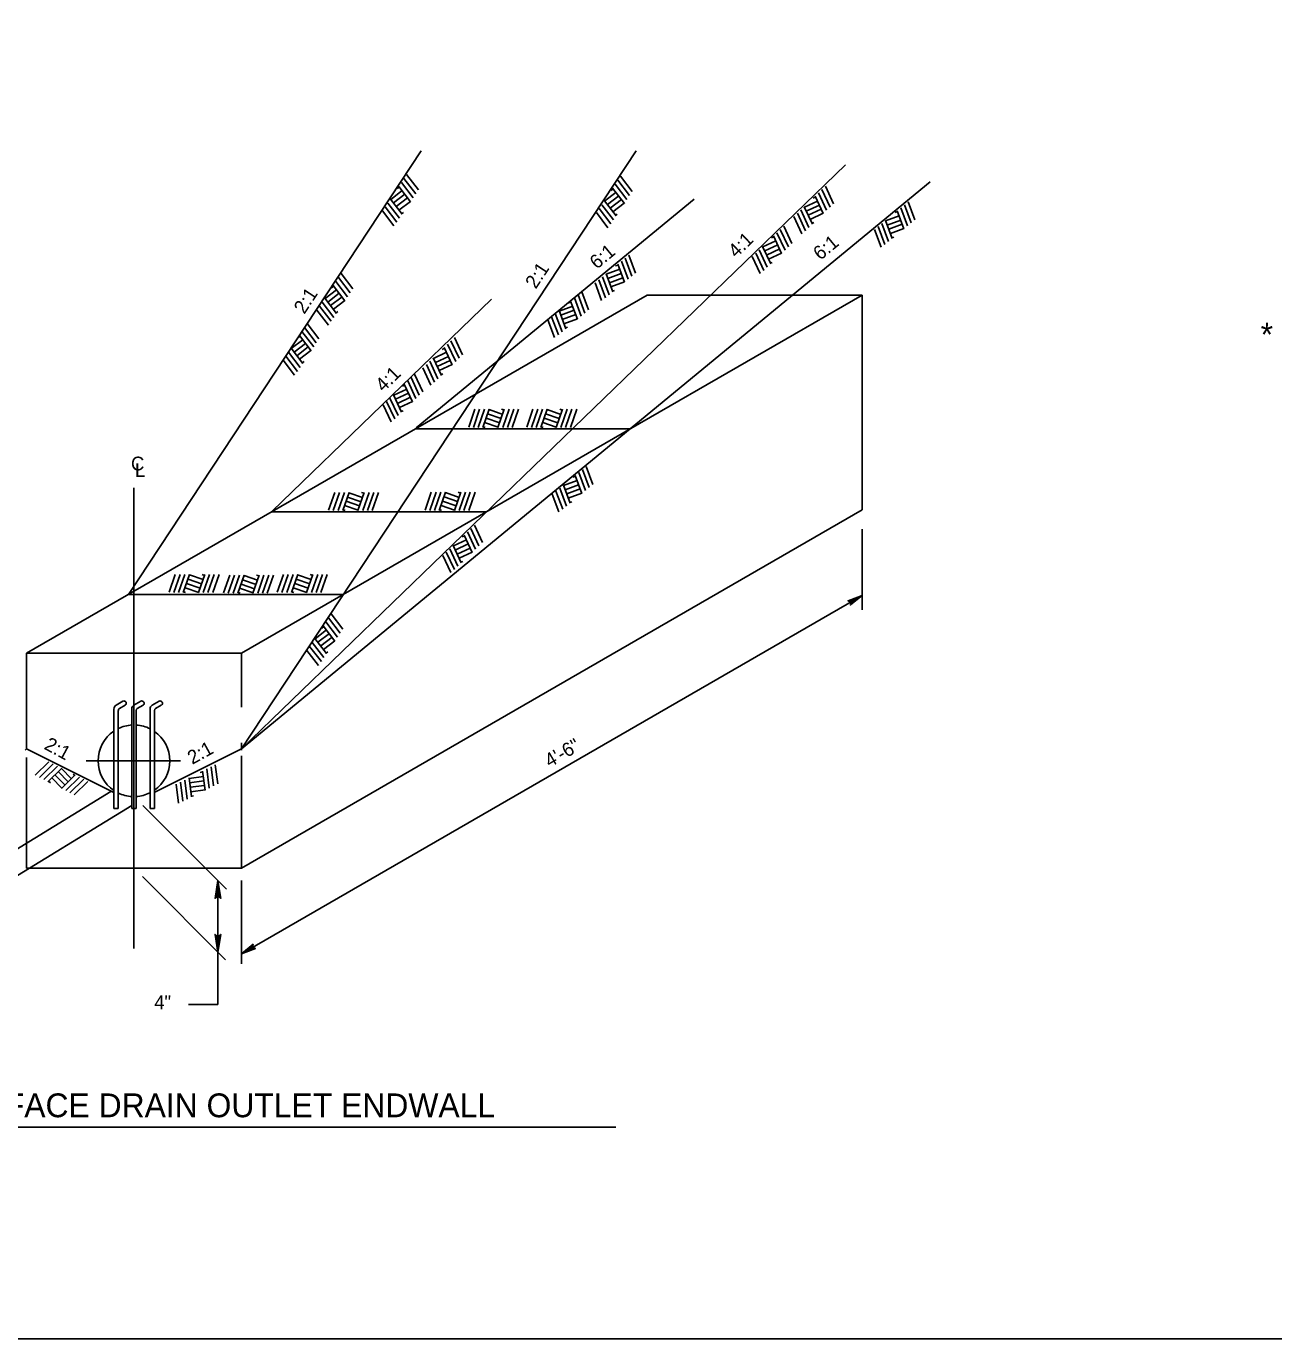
# Model space of a CAD drawing. Extents: x 638877 to 639960, y 297341 to 299123.
# Drawn here: x 639063.9 to 639335.5, y 298544.3 to 298830 of the extents above; entities that cross this region are included whole.
import ezdxf

# ---------------------------------------------------------------- set-up
doc = ezdxf.new("R2010")
doc.units = 0
for name, color, linetype in [('1', 7, 'Continuous'), ('2', 7, 'Continuous'), ('3', 7, 'Continuous')]:
    doc.layers.add(name, color=color, linetype=linetype)

msp = doc.modelspace()

# ---------------------------------------------------------------- linework, layer by layer
at = {"layer": '1'}
for p, q in [((639146.75, 298797.77), (639149.3, 298794.44)), ((639193.32, 298797.39), (639195.86, 298794.07)), ((639145.17, 298795.03), (639144.71, 298794.68)), ((639145.03, 298795.16), (639147.58, 298791.84)), ((639145.6, 298796.03), (639148.15, 298792.71)), ((639146.17, 298796.9), (639148.72, 298793.57)), ((639191.74, 298794.66), (639191.28, 298794.31)), ((639191.6, 298794.79), (639194.15, 298791.47)), ((639192.17, 298795.66), (639194.72, 298792.34)), ((639192.74, 298796.53), (639195.29, 298793.2)), ((639237.91, 298795.2), (639239.67, 298791.4)), ((639143.22, 298792.42), (639145.77, 298789.1)), ((639145.77, 298794.25), (639143.28, 298792.34)), ((639146.37, 298793.47), (639143.88, 298791.57)), ((639146.96, 298792.69), (639144.48, 298790.78)), ((639147.56, 298791.91), (639145.07, 298790)), ((639189.79, 298792.05), (639192.34, 298788.73)), ((639192.34, 298793.88), (639189.85, 298791.97)), ((639192.94, 298793.1), (639190.45, 298791.2)), ((639193.53, 298792.32), (639191.04, 298790.41)), ((639236.19, 298791.98), (639233.35, 298790.66)), ((639235.77, 298792.87), (639235.25, 298792.63)), ((639235.67, 298793.04), (639237.43, 298789.24)), ((639236.41, 298793.76), (639238.18, 298789.96)), ((639237.16, 298794.48), (639238.92, 298790.68)), ((639255.94, 298791.82), (639257.4, 298787.9)), ((639141.5, 298789.82), (639144, 298786.55)), ((639142.08, 298790.69), (639144.62, 298787.36)), ((639142.65, 298791.55), (639145.2, 298788.23)), ((639146.04, 298789.5), (639145.67, 298789.22)), ((639188.07, 298789.45), (639190.57, 298786.18)), ((639188.64, 298790.32), (639191.19, 298786.99)), ((639189.22, 298791.18), (639191.76, 298787.86)), ((639194.13, 298791.54), (639191.64, 298789.63)), ((639192.6, 298789.13), (639192.24, 298788.85)), ((639231.81, 298789.31), (639233.58, 298785.51)), ((639232.56, 298790.03), (639234.33, 298786.23)), ((639233.31, 298790.75), (639235.07, 298786.95)), ((639236.6, 298791.1), (639233.76, 298789.78)), ((639237.02, 298790.2), (639234.18, 298788.88)), ((639237.43, 298789.31), (639234.59, 298787.99)), ((639253.62, 298789.67), (639253.08, 298789.47)), ((639253.53, 298789.84), (639254.99, 298785.91)), ((639254.33, 298790.5), (639255.79, 298786.57)), ((639255.13, 298791.16), (639256.59, 298787.23)), ((639228.85, 298786.54), (639230.61, 298782.74)), ((639231.06, 298788.58), (639232.8, 298784.85)), ((639235.42, 298787.29), (639235, 298787.1)), ((639249.39, 298786.43), (639250.85, 298782.5)), ((639250.19, 298787.09), (639251.65, 298783.16)), ((639251, 298787.75), (639252.45, 298783.82)), ((639253.97, 298788.75), (639251.03, 298787.66)), ((639254.31, 298787.83), (639251.37, 298786.74)), ((639254.65, 298786.91), (639251.71, 298785.82)), ((639254.99, 298785.99), (639252.05, 298784.9)), ((639227.13, 298783.32), (639224.29, 298782)), ((639226.71, 298784.2), (639226.18, 298783.96)), ((639226.6, 298784.37), (639228.37, 298780.57)), ((639227.35, 298785.09), (639229.12, 298781.29)), ((639228.1, 298785.81), (639229.86, 298782.02)), ((639248.59, 298785.77), (639250.02, 298781.91)), ((639252.83, 298784.13), (639252.4, 298783.98)), ((639195.11, 298780.2), (639196.57, 298776.27)), ((639222.75, 298780.64), (639224.52, 298776.84)), ((639223.5, 298781.36), (639225.26, 298777.57)), ((639224.24, 298782.08), (639226.01, 298778.29)), ((639227.54, 298782.43), (639224.7, 298781.11)), ((639227.96, 298781.54), (639225.12, 298780.21)), ((639228.37, 298780.65), (639225.53, 298779.32)), ((639192.8, 298778.05), (639192.25, 298777.85)), ((639192.7, 298778.22), (639194.16, 298774.29)), ((639193.5, 298778.88), (639194.96, 298774.95)), ((639194.3, 298779.54), (639195.76, 298775.61)), ((639222, 298779.92), (639223.74, 298776.19)), ((639226.36, 298778.62), (639225.94, 298778.43)), ((639131.9, 298775.32), (639134.45, 298772)), ((639132.47, 298776.19), (639135.02, 298772.87)), ((639188.56, 298774.81), (639190.02, 298770.88)), ((639189.36, 298775.47), (639190.82, 298771.54)), ((639190.17, 298776.13), (639191.62, 298772.2)), ((639193.14, 298777.13), (639190.2, 298776.04)), ((639193.48, 298776.21), (639190.54, 298775.12)), ((639193.82, 298775.29), (639190.88, 298774.19)), ((639131.49, 298772.67), (639129.01, 298770.77)), ((639132.09, 298771.89), (639129.6, 298769.99)), ((639130.9, 298773.45), (639130.43, 298773.1)), ((639130.75, 298773.59), (639133.3, 298770.26)), ((639131.33, 298774.45), (639133.88, 298771.13)), ((639184.87, 298772.19), (639186.32, 298768.26)), ((639187.76, 298774.15), (639189.19, 298770.29)), ((639194.16, 298774.37), (639191.22, 298773.27)), ((639192, 298772.51), (639191.57, 298772.35)), ((639127.8, 298769.11), (639130.35, 298765.79)), ((639128.37, 298769.98), (639130.92, 298766.65)), ((639128.94, 298770.85), (639131.49, 298767.52)), ((639132.69, 298771.12), (639130.2, 298769.21)), ((639133.28, 298770.33), (639130.8, 298768.43)), ((639182.9, 298769.12), (639179.96, 298768.03)), ((639182.55, 298770.03), (639182.01, 298769.83)), ((639182.46, 298770.21), (639183.92, 298766.28)), ((639183.26, 298770.87), (639184.72, 298766.94)), ((639184.06, 298771.53), (639185.52, 298767.6)), ((639127.22, 298768.24), (639129.73, 298764.98)), ((639131.76, 298767.93), (639131.4, 298767.65)), ((639177.52, 298766.14), (639178.95, 298762.28)), ((639178.32, 298766.8), (639179.78, 298762.87)), ((639179.12, 298767.46), (639180.58, 298763.53)), ((639179.93, 298768.12), (639181.38, 298764.19)), ((639183.24, 298768.2), (639180.3, 298767.11)), ((639183.58, 298767.28), (639180.64, 298766.18)), ((639183.92, 298766.35), (639180.98, 298765.26)), ((639123.97, 298763.55), (639126.52, 298760.23)), ((639124.54, 298764.42), (639127.09, 298761.1)), ((639125.12, 298765.29), (639127.67, 298761.97)), ((639181.76, 298764.5), (639181.33, 298764.34)), ((639124.14, 298761.77), (639121.65, 298759.87)), ((639124.74, 298760.99), (639122.25, 298759.09)), ((639125.33, 298760.22), (639122.85, 298758.31)), ((639123.54, 298762.55), (639123.08, 298762.2)), ((639123.4, 298762.69), (639125.95, 298759.36)), ((639155.66, 298760.82), (639157.43, 298757.02)), ((639156.4, 298761.54), (639158.17, 298757.75)), ((639157.15, 298762.27), (639158.92, 298758.47)), ((639119.87, 298757.34), (639122.37, 298754.08)), ((639120.45, 298758.21), (639122.99, 298754.89)), ((639121.02, 298759.08), (639123.57, 298755.75)), ((639121.59, 298759.95), (639124.14, 298756.62)), ((639125.93, 298759.43), (639123.44, 298757.53)), ((639152.55, 298757.81), (639154.31, 298754.01)), ((639155.43, 298759.05), (639152.59, 298757.73)), ((639155.85, 298758.16), (639153.01, 298756.84)), ((639155.02, 298759.93), (639154.49, 298759.69)), ((639154.91, 298760.1), (639156.68, 298756.3)), ((639124.41, 298757.03), (639124.04, 298756.75)), ((639150.31, 298755.65), (639152.04, 298751.91)), ((639151.05, 298756.37), (639152.82, 298752.57)), ((639151.8, 298757.09), (639153.57, 298753.29)), ((639156.26, 298757.27), (639153.42, 298755.94)), ((639156.67, 298756.37), (639153.83, 298755.05)), ((639146.35, 298751.92), (639145.82, 298751.68)), ((639146.24, 298752.09), (639148.01, 298748.29)), ((639146.99, 298752.81), (639148.76, 298749.01)), ((639147.73, 298753.53), (639149.5, 298749.74)), ((639148.49, 298754.26), (639150.25, 298750.46)), ((639154.66, 298754.35), (639154.25, 298754.16)), ((639143.13, 298749.08), (639144.9, 298745.28)), ((639143.88, 298749.8), (639145.65, 298746)), ((639146.77, 298751.04), (639143.93, 298749.72)), ((639147.18, 298750.15), (639144.34, 298748.83)), ((639147.59, 298749.26), (639144.75, 298747.93)), ((639141.64, 298747.64), (639143.37, 298743.9)), ((639142.39, 298748.36), (639144.15, 298744.56)), ((639148.01, 298748.36), (639145.17, 298747.04)), ((639145.99, 298746.34), (639145.58, 298746.15)), ((639161.61, 298746.65), (639160.26, 298742.77)), ((639162.65, 298746.65), (639161.28, 298742.69)), ((639163.69, 298746.65), (639162.32, 298742.69)), ((639164.73, 298746.65), (639163.36, 298742.69)), ((639167.66, 298745.53), (639164.7, 298746.56)), ((639168.01, 298746.65), (639166.64, 298742.69)), ((639167.98, 298746.46), (639167.43, 298746.65)), ((639169.05, 298746.65), (639167.68, 298742.69)), ((639170.09, 298746.65), (639168.72, 298742.69)), ((639171.13, 298746.65), (639169.76, 298742.69)), ((639174.25, 298746.65), (639172.9, 298742.76)), ((639175.29, 298746.65), (639173.91, 298742.69)), ((639176.33, 298746.65), (639174.95, 298742.69)), ((639177.37, 298746.65), (639175.99, 298742.69)), ((639180.29, 298745.53), (639177.33, 298746.56)), ((639180.65, 298746.65), (639179.28, 298742.69)), ((639180.61, 298746.46), (639180.07, 298746.65)), ((639181.69, 298746.65), (639180.32, 298742.69)), ((639182.73, 298746.65), (639181.36, 298742.69)), ((639183.77, 298746.65), (639182.4, 298742.69)), ((639166.69, 298742.75), (639163.73, 298743.77)), ((639167.02, 298743.68), (639164.05, 298744.7)), ((639167.34, 298744.61), (639164.38, 298745.63)), ((639179.33, 298742.75), (639176.37, 298743.77)), ((639179.65, 298743.68), (639176.69, 298744.7)), ((639179.97, 298744.6), (639177.01, 298745.63)), ((639163.84, 298742.69), (639163.41, 298742.85)), ((639176.48, 298742.69), (639176.05, 298742.84)), ((639183.5, 298732.05), (639182.96, 298731.85)), ((639183.41, 298732.22), (639184.86, 298728.3)), ((639184.21, 298732.88), (639185.67, 298728.96)), ((639185.01, 298733.54), (639186.47, 298729.62)), ((639185.82, 298734.21), (639187.27, 298730.28)), ((639179.26, 298728.82), (639180.72, 298724.89)), ((639180.07, 298729.48), (639181.52, 298725.55)), ((639180.87, 298730.14), (639182.33, 298726.21)), ((639183.84, 298731.14), (639180.91, 298730.04)), ((639184.19, 298730.22), (639181.25, 298729.13)), ((639184.53, 298729.3), (639181.59, 298728.2)), ((639131.12, 298728.56), (639129.77, 298724.68)), ((639132.16, 298728.56), (639130.78, 298724.6)), ((639133.2, 298728.56), (639131.82, 298724.6)), ((639134.24, 298728.56), (639132.86, 298724.6)), ((639136.52, 298725.59), (639133.56, 298726.61)), ((639136.84, 298726.52), (639133.88, 298727.54)), ((639137.16, 298727.44), (639134.2, 298728.47)), ((639137.52, 298728.56), (639136.15, 298724.6)), ((639137.48, 298728.37), (639136.94, 298728.56)), ((639138.56, 298728.56), (639137.19, 298724.6)), ((639139.6, 298728.56), (639138.23, 298724.6)), ((639140.64, 298728.56), (639139.27, 298724.6)), ((639152.12, 298728.59), (639150.77, 298724.71)), ((639153.16, 298728.59), (639151.79, 298724.63)), ((639154.2, 298728.59), (639152.83, 298724.63)), ((639155.24, 298728.59), (639153.87, 298724.63)), ((639157.53, 298725.62), (639154.56, 298726.64)), ((639157.85, 298726.55), (639154.89, 298727.57)), ((639158.17, 298727.47), (639155.21, 298728.5)), ((639158.52, 298728.59), (639157.15, 298724.63)), ((639158.49, 298728.4), (639157.94, 298728.59)), ((639159.56, 298728.59), (639158.19, 298724.63)), ((639160.6, 298728.59), (639159.23, 298724.63)), ((639161.64, 298728.59), (639160.27, 298724.63)), ((639178.46, 298728.16), (639179.89, 298724.3)), ((639184.87, 298728.37), (639181.93, 298727.28)), ((639182.7, 298726.52), (639182.27, 298726.36)), ((639133.35, 298724.6), (639132.92, 298724.76)), ((639136.2, 298724.66), (639133.24, 298725.68)), ((639154.35, 298724.63), (639153.92, 298724.79)), ((639157.2, 298724.69), (639154.24, 298725.71)), ((639160.74, 298720.71), (639162.5, 298716.91)), ((639161.49, 298721.43), (639163.25, 298717.63)), ((639159.77, 298718.21), (639156.93, 298716.89)), ((639159.35, 298719.1), (639158.82, 298718.86)), ((639159.24, 298719.26), (639161.01, 298715.46)), ((639159.99, 298719.99), (639161.76, 298716.19)), ((639154.64, 298714.81), (639156.38, 298711.08)), ((639155.39, 298715.53), (639157.16, 298711.73)), ((639156.14, 298716.26), (639157.9, 298712.46)), ((639156.88, 298716.98), (639158.65, 298713.18)), ((639160.18, 298717.32), (639157.34, 298716)), ((639160.6, 298716.43), (639157.76, 298715.11)), ((639161.01, 298715.54), (639158.17, 298714.21)), ((639159, 298713.51), (639158.58, 298713.33)), ((639096.4, 298710.68), (639095.05, 298706.79)), ((639097.44, 298710.68), (639096.06, 298706.72)), ((639098.48, 298710.68), (639097.1, 298706.72)), ((639099.52, 298710.68), (639098.14, 298706.72)), ((639102.12, 298708.63), (639099.16, 298709.66)), ((639102.44, 298709.56), (639099.48, 298710.59)), ((639102.8, 298710.68), (639101.43, 298706.72)), ((639102.76, 298710.49), (639102.22, 298710.68)), ((639103.84, 298710.68), (639102.47, 298706.72)), ((639104.88, 298710.68), (639103.51, 298706.72)), ((639105.92, 298710.68), (639104.55, 298706.72)), ((639108.26, 298710.55), (639106.91, 298706.66)), ((639109.3, 298710.55), (639107.93, 298706.59)), ((639110.34, 298710.55), (639108.97, 298706.59)), ((639111.38, 298710.55), (639110.01, 298706.59)), ((639113.99, 298708.5), (639111.03, 298709.53)), ((639114.31, 298709.43), (639111.35, 298710.45)), ((639114.66, 298710.55), (639113.29, 298706.59)), ((639114.63, 298710.36), (639114.08, 298710.55)), ((639115.7, 298710.55), (639114.33, 298706.59)), ((639116.74, 298710.55), (639115.37, 298706.59)), ((639117.78, 298710.55), (639116.41, 298706.59)), ((639119.95, 298710.68), (639118.6, 298706.79)), ((639120.99, 298710.68), (639119.61, 298706.72)), ((639122.03, 298710.68), (639120.65, 298706.72)), ((639123.07, 298710.68), (639121.69, 298706.72)), ((639125.67, 298708.63), (639122.71, 298709.66)), ((639125.99, 298709.56), (639123.03, 298710.59)), ((639126.35, 298710.68), (639124.98, 298706.72)), ((639126.31, 298710.49), (639125.77, 298710.68)), ((639127.39, 298710.68), (639126.02, 298706.72)), ((639128.43, 298710.68), (639127.06, 298706.72)), ((639129.47, 298710.68), (639128.1, 298706.72)), ((639098.63, 298706.72), (639098.2, 298706.87)), ((639101.48, 298706.78), (639098.52, 298707.8)), ((639101.8, 298707.71), (639098.84, 298708.73)), ((639110.49, 298706.59), (639110.06, 298706.74)), ((639113.34, 298706.65), (639110.38, 298707.67)), ((639113.67, 298707.57), (639110.7, 298708.6)), ((639122.18, 298706.72), (639121.75, 298706.87)), ((639125.03, 298706.78), (639122.07, 298707.8)), ((639125.35, 298707.71), (639122.39, 298708.73)), ((639129.17, 298700.37), (639131.71, 298697.05)), ((639129.73, 298701.24), (639132.29, 298697.91)), ((639130.31, 298702.11), (639132.86, 298698.78)), ((639129.33, 298698.59), (639126.85, 298696.68)), ((639129.93, 298697.81), (639127.44, 298695.91)), ((639128.73, 298699.37), (639128.27, 298699.02)), ((639128.59, 298699.5), (639131.14, 298696.18)), ((639125.64, 298695.03), (639128.19, 298691.7)), ((639126.21, 298695.89), (639128.76, 298692.57)), ((639126.78, 298696.76), (639129.33, 298693.44)), ((639130.53, 298697.03), (639128.04, 298695.12)), ((639131.12, 298696.25), (639128.63, 298694.34)), ((639125.06, 298694.16), (639127.57, 298690.89)), ((639129.6, 298693.84), (639129.23, 298693.56))]:
    msp.add_line(p, q, dxfattribs=at)
msp.add_lwpolyline([(639703.19, 298544.28), (639703.19, 299108.28), (638917.19, 299108.28), (638917.19, 298544.28), (639703.19, 298544.28), (639703.19, 298570.64), (639503.19, 298570.64), (639503.19, 298635.32), (639703.19, 298635.32), (639703.19, 298664.28), (639503.19, 298664.28), (639503.19, 298544.28), (639581.99, 298544.28), (639581.99, 298570.64), (639581.99, 298544.28), (639658.99, 298544.28), (639658.99, 298570.64), (639658.99, 298558.33), (639703.19, 298558.33)], dxfattribs=at)
at = {"layer": '2'}
for p, q in [((639086.18, 298706.33), (639149.93, 298802.91)), ((639110.79, 298672.72), (639196.73, 298802.91)), ((639110.79, 298672.72), (639242.26, 298799.85)), ((639110.79, 298672.72), (639260.73, 298796.14)), ((639148.85, 298742.57), (639209.38, 298792.4)), ((639117.47, 298724.44), (639165.23, 298770.62)), ((639149.17, 298742.7), (639199.09, 298771.52)), ((639195.57, 298742.46), (639245.89, 298771.52)), ((639199.09, 298771.52), (639245.89, 298771.52)), ((639245.89, 298724.72), (639245.89, 298771.52)), ((639063.99, 298693.52), (639149.17, 298742.7)), ((639110.79, 298693.52), (639195.57, 298742.46)), ((639195.41, 298742.38), (639148.61, 298742.38)), ((639087.39, 298729.53), (639087.39, 298629.26)), ((639110.79, 298646.72), (639245.89, 298724.72)), ((639164.17, 298724.34), (639117.37, 298724.34)), ((639245.89, 298702.99), (639245.89, 298720.56)), ((639132.98, 298706.33), (639086.18, 298706.33)), ((639110.79, 298628.1), (639245.89, 298706.1)), ((639110.79, 298693.52), (639063.99, 298693.52)), ((639063.99, 298693.52), (639063.99, 298672.72)), ((639110.79, 298681.78), (639110.79, 298693.52)), ((639083.51, 298682.22), (639084.99, 298683.08)), ((639087.39, 298682.22), (639088.88, 298683.08)), ((639091.38, 298682.22), (639092.86, 298683.08)), ((639083.02, 298659.72), (639083.02, 298681.37)), ((639083.99, 298659.72), (639083.99, 298681.09)), ((639084.24, 298681.51), (639085.48, 298682.23)), ((639086.91, 298659.72), (639086.91, 298681.37)), ((639087.88, 298659.72), (639087.88, 298681.09)), ((639088.12, 298681.51), (639089.37, 298682.23)), ((639090.89, 298659.72), (639090.89, 298681.37)), ((639091.86, 298659.72), (639091.86, 298681.09)), ((639092.11, 298681.51), (639093.35, 298682.23)), ((639063.7, 298672.43), (639064, 298672.73)), ((639083.01, 298663.21), (639063.99, 298672.72)), ((639091.94, 298663.29), (639110.79, 298672.72)), ((639110.79, 298672.42), (639110.79, 298674.01)), ((639063.99, 298670.85), (639063.99, 298646.72)), ((639065.88, 298666.95), (639068.87, 298669.88)), ((639066.81, 298666.49), (639069.81, 298669.42)), ((639067.74, 298666.03), (639070.73, 298668.95)), ((639076.99, 298670.12), (639097.55, 298670.12)), ((639104.17, 298668.79), (639104.72, 298664.64)), ((639105.1, 298669.26), (639105.65, 298665.1)), ((639110.79, 298646.72), (639110.79, 298671.17)), ((639068.67, 298665.56), (639071.67, 298668.48)), ((639069.49, 298666.4), (639071.67, 298664.16)), ((639070.19, 298667.09), (639072.37, 298664.85)), ((639070.89, 298667.77), (639073.08, 298665.53)), ((639071.59, 298668.46), (639073.79, 298666.22)), ((639071.61, 298664.09), (639074.6, 298667.02)), ((639072.53, 298663.63), (639075.53, 298666.55)), ((639073.47, 298663.16), (639076.46, 298666.09)), ((639074.17, 298667.23), (639074.49, 298666.91)), ((639098.44, 298665.93), (639098.99, 298661.77)), ((639099.38, 298666.39), (639099.92, 298662.24)), ((639102.5, 298666.7), (639099.39, 298666.29)), ((639102.36, 298667.68), (639101.79, 298667.6)), ((639102.31, 298667.86), (639102.86, 298663.71)), ((639103.24, 298668.33), (639103.78, 298664.17)), ((638966.19, 298592.22), (639082.38, 298663.46)), ((639068.79, 298665.71), (639069.19, 298665.3)), ((639074.39, 298662.69), (639077.34, 298665.57)), ((639096.58, 298665), (639097.12, 298660.92)), ((639097.52, 298665.46), (639098.06, 298661.31)), ((639102.62, 298665.73), (639099.52, 298665.32)), ((639102.75, 298664.76), (639099.64, 298664.34)), ((639102.88, 298663.78), (639099.77, 298663.37)), ((638976.94, 298592.96), (639086.92, 298660.4)), ((639107.52, 298642.19), (639089.3, 298660.41)), ((639100.35, 298662.46), (639099.9, 298662.4)), ((639083.02, 298659.72), (639083.99, 298659.72)), ((639086.91, 298659.72), (639087.88, 298659.72)), ((639090.89, 298659.72), (639091.86, 298659.72)), ((639063.99, 298646.72), (639110.79, 298646.72)), ((639107.34, 298626.77), (639089.22, 298644.89)), ((639105.68, 298628.43), (639105.68, 298644.03)), ((639110.79, 298625.9), (639110.79, 298644.06)), ((639105.68, 298617.08), (639105.68, 298628.43)), ((639105.68, 298617.08), (639099.25, 298617.08))]:
    msp.add_line(p, q, dxfattribs=at)
for centre, radius, start, end in [((639085.24, 298682.65), 0.488, 300.0477, 120.0477), ((639089.12, 298682.65), 0.488, 300.0477, 120.0477), ((639093.11, 298682.65), 0.488, 300.0477, 120.0477), ((639084, 298681.37), 0.977, 120.0082, 180), ((639084.48, 298681.09), 0.487, 120.0082, 180), ((639087.88, 298681.37), 0.977, 120.0082, 180), ((639088.36, 298681.09), 0.487, 120.0082, 180), ((639091.87, 298681.37), 0.977, 120.0082, 180), ((639092.35, 298681.09), 0.487, 120.0082, 180), ((639087.39, 298670.12), 7.8, 93.3327, 115.6549), ((639087.39, 298670.12), 7.8, 63.196, 86.2661), ((639087.39, 298670.12), 7.8, 124.3186, 236.0108), ((639087.39, 298670.12), 7.8, 304.9141, 54.9847), ((639087.39, 298670.12), 7.8, 244.2051, 266.8202), ((639087.39, 298670.12), 7.8, 273.5607, 296.3333)]:
    msp.add_arc(centre, radius, start, end, dxfattribs=at)
at = {"layer": '3'}
for p, q in [((639148.61, 298742.38), (639148.61, 298742.38)), ((639195.41, 298742.38), (639195.41, 298742.38)), ((639117.37, 298724.34), (639117.37, 298724.34)), ((639164.17, 298724.34), (639164.17, 298724.34)), ((639086.18, 298706.33), (639086.18, 298706.33)), ((639130.34, 298705.23), (639130.34, 298705.23)), ((639027.1, 298590.34), (639192.27, 298590.34))]:
    msp.add_line(p, q, dxfattribs=at)
for points in [[(639243.04, 298704.9), (639243.25, 298704.76), (639245.89, 298706.1), (639243.04, 298704.9), (639242.84, 298704.94), (639245.89, 298706.1), (639243.41, 298704.5), (639243.43, 298704.25), (639245.89, 298706.1), (639243.36, 298704.04), (639243.43, 298704.25)], [(639105.22, 298640.35), (639105.48, 298640.48), (639105.68, 298644.03), (639105.22, 298640.35), (639105.06, 298640.16), (639105.68, 298644.03), (639105.85, 298640.49), (639106.12, 298640.36), (639105.68, 298644.03), (639106.29, 298640.16), (639106.12, 298640.36)], [(639106.14, 298632.12), (639105.88, 298631.98), (639105.68, 298628.43), (639106.14, 298632.12), (639106.3, 298632.3), (639105.68, 298628.43), (639105.51, 298631.98), (639105.24, 298632.1), (639105.68, 298628.43), (639105.07, 298632.3), (639105.24, 298632.1)], [(639113.64, 298629.3), (639113.43, 298629.44), (639110.79, 298628.1), (639113.64, 298629.3), (639113.85, 298629.26), (639110.79, 298628.1), (639113.27, 298629.7), (639113.26, 298629.95), (639110.79, 298628.1), (639113.33, 298630.16), (639113.26, 298629.95)]]:
    msp.add_lwpolyline(points, dxfattribs=at)

# ---------------------------------------------------------------- texts
at = {"layer": '1'}
msp.add_text('*', height=5.18, dxfattribs=at).set_placement((639332.67, 298760.33))
at = {"layer": '3'}
for s, rotation, p in [('4:1', 44.064, (639218.49, 298779.46)), ('6:1', 39.479, (639236.8, 298778.96)), ('6:1', 39.479, (639188.15, 298777.01)), ('2:1', 56.5635, (639174.86, 298772.68)), ('2:1', 56.5635, (639124.47, 298767.19)), ('4:1', 44.064, (639141.7, 298750.25)), ('2:1', 331.5635, (639067.65, 298672.79)), ('4\'-6"', 29.9998, (639177.89, 298668.57)), ('2:1', 28.7635, (639100.09, 298669.22))]:
    msp.add_text(s, height=3, rotation=rotation, dxfattribs=at).set_placement(p)
for s, height, p in [('C', 3, (639086.75, 298733.33)), ('L', 3, (639087.61, 298731.9)), ('4"', 3, (639091.81, 298616.02)), ('SUBSURFACE DRAIN OUTLET ENDWALL', 5.1858, (639030.38, 298592.51))]:
    msp.add_text(s, height=height, dxfattribs=at).set_placement(p)

doc.saveas('drawing.dxf')
